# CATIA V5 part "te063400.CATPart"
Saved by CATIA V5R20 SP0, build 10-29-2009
Part number: 1
Definition: NONE
Nomenclature: 1
Source: Unknown
Description: PART-1-DESC
Bounding box of the stored display mesh (mm): x 0 to 400, y -3 to 3, z -2.853 to 2.853
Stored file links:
  C:\Users\Utente\Desktop\IO LAVORO\3D X SITO CF\CUMSA\3D files TE\te063400.CATPart
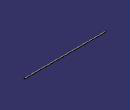
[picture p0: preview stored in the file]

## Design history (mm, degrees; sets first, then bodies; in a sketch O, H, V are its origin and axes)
Body1 "1" (main body)
  Solid1: solid without history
